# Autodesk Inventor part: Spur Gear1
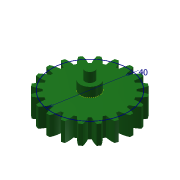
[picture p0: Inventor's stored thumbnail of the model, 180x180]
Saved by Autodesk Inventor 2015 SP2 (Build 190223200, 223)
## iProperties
Created: 2019-12
Part Number: Spur Gear1
Material: Steel
Document SubType Name: Modeling
Designer: Kuan_Lun Hsu
Categories: <?xml version="1.0" encoding="UTF-16"?> <MemberInstance><Categories><FamilyTemplate><FamilyTemplateParameter ValueType="xs:double" Id="1" ObjectReferenceKey="da
Density: 7.85 g/cm^3
Appearance: 平滑 - 深森林綠
Mass: 101.709 g
Surface Area: 52.5838 cm^2
Volume: 12.9565 cm^3
CustomPartVersion: 1
Author: Kuan_Lun Hsu
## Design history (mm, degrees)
sketch "Sketch1"
  geometry: C1 r 22 at (0, 0)
  constraints: 1 centre point
  dimensions: "d0" = 44 diameter of C1 (= da_da)
extrude "Extrusion1" new body sketch "Sketch1" distance "d1" = 10 (= da_b); taper "d2" = 0 deg
workplane "Work Plane2"
sketch "Sketch2"
  geometry: C1 r 22 at (0, 0) reference; C2 r 20 at (0, 0)
  constraints: 1 centre point, 1 coincident
  dimensions: "d3" = 40 diameter of C2 (= da_dw)
feature "節圓直徑" sketch "Sketch2" dims "d4" = 10, "d5" = 0
workplane "Work Plane8"
workplane "Work Plane9"
feature "正齒輪" dims "da_b" = 10, "da_d" = 40, "da_aw" = 60, "da_da" = 44, "da_df" = 35, "da_dw" = 40, angle "da_beta" = 0 deg, "da_lefttooth" = 0, "da_righttooth" = 0
sketch "草圖3"
  geometry: C1 r 2.5 at (0, 0); C2 r 5 at (0, 0); 1 further point
  constraints: 2 centre point, 2 coincident
  dimensions: "d49" = 5 diameter of C1; "d50" = 10 diameter of C2
extrude "擠出2" join sketch "草圖3" distance "d51" = 5; taper "d52" = 0 deg
extrude "擠出3" join sketch "草圖3" distance "d53" = 10; taper "d54" = 0 deg
node "工作平面11"
sketch "草圖4"
  geometry: C1 r 5 at (0, 0) reference; C2 r 20 at (0, 0); 1 further point
  constraints: 1 centre point, 1 coincident
  dimensions: "d55" = 40 diameter of C2
body "Solid1"
body "Srf1"
other parameters: "d17" = 0, "d34" = 9 deg (computed from da_z), "d39" = 0, "d41" = 0, "d47" = 0, "d48" = 0
